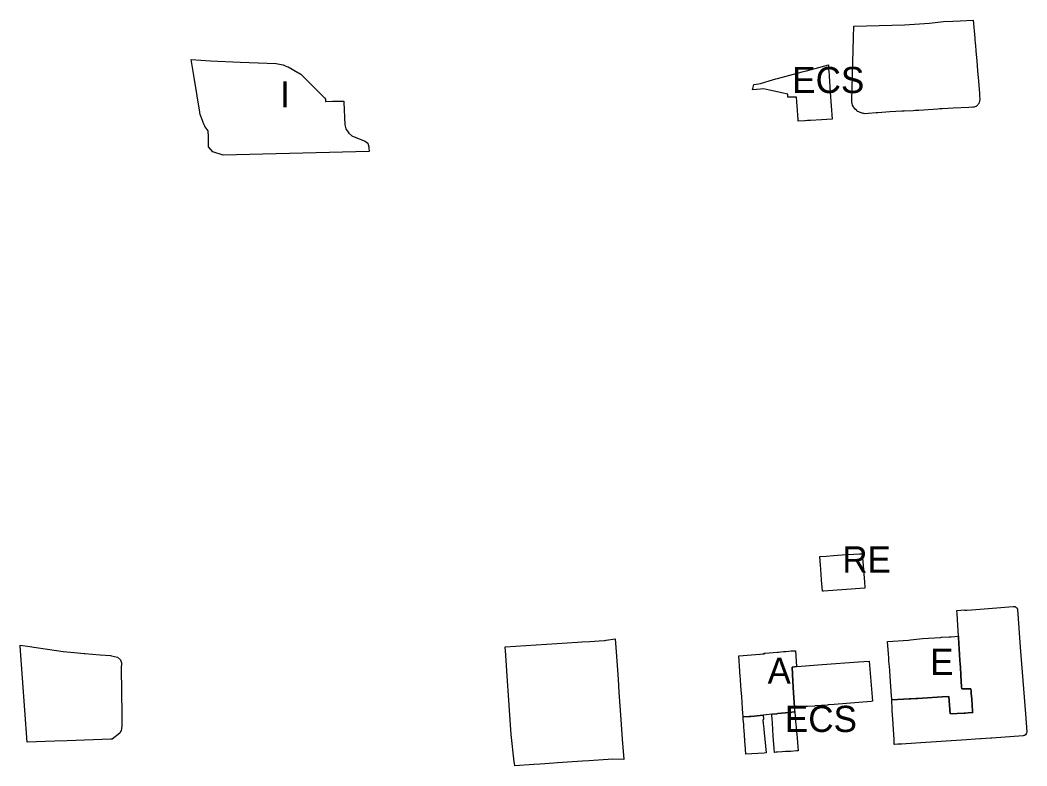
# Model space of a CAD drawing. Extents: x 603332 to 610661, y 4407453 to 4413433.
# Drawn here: x 607234.2 to 607695.4, y 4411729.9 to 4412071.6 of the extents above; entities that cross this region are included whole.
import ezdxf

# ---------------------------------------------------------------- set-up
doc = ezdxf.new("R2010")
doc.units = 0
for name, color, linetype in [('Sistema General-Equipament Privat. Església', 7, 'Continuous'), ('Sistema General-Equipament Públic', 7, 'Continuous'), ('Sistema General-Equipament Públic Socio-cultural', 7, 'Continuous'), ('Sistema General-Equipament Públic-Ajuntament', 7, 'Continuous'), ('Sistema General-Equipament Públic. Sales reunió i espectacles', 7, 'Continuous'), ('Sistema General-Espai Lliure Públic', 7, 'Continuous'), ('Sistema General-Espai Lliure Públic-Sòl Rústic', 7, 'Continuous'), ('Sistema General-Infraestructures', 7, 'Continuous')]:
    doc.layers.add(name, color=color, linetype=linetype)

msp = doc.modelspace()

# ---------------------------------------------------------------- linework, layer by layer
at = {"layer": 'Sistema General-Equipament Privat. Església'}
msp.add_lwpolyline([(607633.47, 4411760.08), (607633.46, 4411760.27), (607633.31, 4411762.33), (607633.21, 4411763.69), (607633.17, 4411764.29), (607632.88, 4411768.41), (607632.52, 4411773.5), (607632.37, 4411775.55), (607632.31, 4411776.45), (607632.2, 4411777.95), (607632.19, 4411778.1), (607632.19, 4411778.13), (607632.18, 4411778.23), (607632.1, 4411779.44), (607631.97, 4411781.23), (607631.57, 4411786.88), (607641.21, 4411787.54), (607642.09, 4411787.6), (607647.54, 4411788.26), (607655.73, 4411788.77), (607656.32, 4411788.81), (607659.75, 4411789.02), (607660.63, 4411789.08), (607664.02, 4411789.33), (607664.04, 4411788.97), (607664.25, 4411785.61), (607664.36, 4411783.76), (607664.55, 4411780.62), (607664.82, 4411776.35), (607664.89, 4411775.23), (607665.13, 4411771.29), (607665.45, 4411766.06), (607665.51, 4411765.15), (607665.63, 4411765.15), (607665.65, 4411765.15), (607665.81, 4411765.15), (607666.48, 4411765.17), (607668.97, 4411765.21), (607669.72, 4411765.22), (607669.76, 4411764.75), (607669.78, 4411764.37), (607669.89, 4411762.99), (607670.08, 4411760.51), (607670.5, 4411754.9), (607670.55, 4411754.26), (607668.44, 4411754.16), (607667.04, 4411754.09), (607666.7, 4411754.08), (607660.18, 4411753.77), (607659.62, 4411761.64), (607656.5, 4411761.45), (607647.48, 4411760.92), (607645.36, 4411760.79), (607644.45, 4411760.73), (607642.21, 4411760.6), (607641.51, 4411760.56)], close=True, dxfattribs=at)
at = {"layer": 'Sistema General-Equipament Públic'}
msp.add_lwpolyline([(607575.9, 4411735.79), (607575.89, 4411735.79), (607575.07, 4411735.74), (607572.06, 4411735.54), (607566.63, 4411735.18), (607566.46, 4411737.59), (607566.18, 4411741.36), (607565.82, 4411746.38), (607565.75, 4411747.28), (607565.63, 4411748.93), (607565.47, 4411751.13), (607565.39, 4411752.34), (607568.14, 4411752.51), (607568.86, 4411752.56), (607570.42, 4411752.73), (607574.53, 4411753.18), (607574.54, 4411753.18), (607574.78, 4411751.06), (607574.42, 4411751.02), (607574.61, 4411749.22), (607574.83, 4411746.86), (607575.03, 4411744.8), (607575.29, 4411742.1), (607575.9, 4411735.8)], close=True, dxfattribs=at)
at = {"layer": 'Sistema General-Equipament Públic Socio-cultural'}
for points in [[(607590.55, 4412025.27), (607590.55, 4412025.51), (607590.56, 4412026.13), (607590.07, 4412032.25), (607589.98, 4412034.11), (607589.86, 4412036.36), (607589.22, 4412036.36), (607587.77, 4412036.37), (607585.78, 4412036.37), (607585.85, 4412037.75), (607582.96, 4412038.3), (607581.74, 4412038.53), (607577.48, 4412039.47), (607574.75, 4412040.05), (607573.36, 4412040), (607569.67, 4412039.72), (607570.22, 4412042.04), (607572.39, 4412042.4), (607573.34, 4412042.56), (607577.23, 4412043.76), (607578.85, 4412044.25), (607580.35, 4412044.71), (607581.06, 4412044.9), (607592.45, 4412047.92), (607593.7, 4412048.25), (607594.35, 4412048.42), (607597.74, 4412049.32), (607598.45, 4412049.51), (607604.41, 4412051.09), (607604.46, 4412050.37), (607604.46, 4412050.29), (607604.56, 4412048.89), (607604.58, 4412048.56), (607604.75, 4412046.1), (607604.76, 4412046.03), (607605.28, 4412038.38), (607606.12, 4412026.25), (607601.26, 4412025.94), (607596.2, 4412025.63), (607594.84, 4412025.54), (607593.83, 4412025.48), (607593.61, 4412025.46)], [(607590.6, 4411736.77), (607589.87, 4411736.72), (607587.25, 4411736.54), (607587.06, 4411736.53), (607586.8, 4411736.52), (607586.38, 4411736.49), (607585.58, 4411736.43), (607584.95, 4411736.39), (607583.31, 4411736.28), (607581.07, 4411736.14), (607580.55, 4411736.1), (607579.84, 4411736.05), (607579.74, 4411736.05), (607579.61, 4411737.78), (607579.17, 4411743.48), (607578.93, 4411746.61), (607578.76, 4411749.54), (607578.66, 4411751.37), (607578.5, 4411753.06), (607578.45, 4411753.57), (607578.46, 4411753.58), (607580.77, 4411753.8), (607581.24, 4411753.84), (607586.45, 4411754.36), (607588.97, 4411754.6), (607588.96, 4411754.75), (607589.06, 4411754.76), (607589.07, 4411754.66), (607589.1, 4411754.17), (607589.21, 4411752.79), (607589.31, 4411751.54), (607589.32, 4411751.37), (607589.32, 4411751.35), (607589.33, 4411751.22), (607589.42, 4411750.2), (607589.53, 4411749.05), (607589.67, 4411747.45), (607589.73, 4411746.75), (607589.74, 4411746.64), (607589.76, 4411746.45), (607589.84, 4411745.58), (607589.88, 4411745.1), (607589.94, 4411744.44)]]:
    msp.add_lwpolyline(points, close=True, dxfattribs=at)
at = {"layer": 'Sistema General-Equipament Públic-Ajuntament'}
msp.add_lwpolyline([(607589.77, 4411775.35), (607587.84, 4411775.14), (607588.19, 4411768.73), (607588.49, 4411763.29), (607588.84, 4411756.76), (607588.95, 4411754.75), (607588.96, 4411754.75), (607588.97, 4411754.6), (607586.45, 4411754.36), (607581.24, 4411753.84), (607580.77, 4411753.8), (607578.46, 4411753.58), (607578.45, 4411753.57), (607575.98, 4411753.32), (607574.54, 4411753.18), (607574.53, 4411753.18), (607570.42, 4411752.73), (607568.86, 4411752.56), (607568.14, 4411752.51), (607565.39, 4411752.34), (607565.37, 4411752.64), (607565.27, 4411753.9), (607565.11, 4411756.18), (607564.71, 4411761.62), (607564.5, 4411764.58), (607564.17, 4411769.19), (607564.12, 4411769.86), (607564.11, 4411769.95), (607564.11, 4411770.03), (607564.06, 4411770.62), (607563.87, 4411773.27), (607563.36, 4411780.33), (607573.01, 4411781.07), (607573.24, 4411781.09), (607574.45, 4411781.17), (607575.1, 4411781.22), (607575.08, 4411781.48), (607575.39, 4411781.51), (607575.4, 4411781.51), (607575.52, 4411781.52), (607581, 4411782), (607581.54, 4411782.05), (607582.7, 4411782.15), (607583.87, 4411782.26), (607584.93, 4411782.35), (607586.26, 4411782.47), (607587.45, 4411782.53), (607589.4, 4411782.63)], close=True, dxfattribs=at)
at = {"layer": 'Sistema General-Equipament Públic. Sales reunió i espectacles'}
msp.add_lwpolyline([(607621.12, 4411811.36), (607602.21, 4411809.9), (607601.73, 4411809.86), (607601.3, 4411814.99), (607601.12, 4411817.68), (607600.98, 4411819.87), (607600.95, 4411820.21), (607600.82, 4411821.71), (607600.51, 4411825.78), (607603.55, 4411826), (607606.77, 4411826.23), (607610.73, 4411826.54), (607618.67, 4411826.99), (607619.98, 4411827.08), (607620.37, 4411821.65), (607620.93, 4411814.01), (607621.09, 4411811.69), (607621.1, 4411811.58), (607621.1, 4411811.52)], close=True, dxfattribs=at)
at = {"layer": 'Sistema General-Espai Lliure Públic'}
for points in [[(607616.07, 4412068.82), (607639.3, 4412069.47), (607650.77, 4412070.28), (607657.19, 4412070.9), (607661.42, 4412071.12), (607664.8, 4412071.29), (607670.8, 4412071.6), (607671.52, 4412063.27), (607671.57, 4412062.71), (607671.57, 4412062.62), (607671.68, 4412061.33), (607671.72, 4412060.93), (607671.73, 4412060.84), (607671.78, 4412060.19), (607672.03, 4412057.33), (607672.41, 4412052.88), (607672.81, 4412048.29), (607673.17, 4412043.63), (607673.61, 4412037.97), (607673.7, 4412036.88), (607673.81, 4412035.39), (607673.72, 4412034.38), (607673.71, 4412034.36), (607673.69, 4412034.29), (607673.55, 4412033.94), (607673.38, 4412033.47), (607673.06, 4412033.02), (607672.87, 4412032.75), (607672.84, 4412032.71), (607672.82, 4412032.68), (607672.07, 4412032.07), (607672.03, 4412032.05), (607672.02, 4412032.04), (607671.25, 4412031.69), (607670.55, 4412031.65), (607668.76, 4412031.57), (607661.58, 4412031.24), (607659.15, 4412031.12), (607656.49, 4412030.95), (607655.42, 4412030.88), (607654.63, 4412030.83), (607645.86, 4412030.25), (607644.37, 4412030.15), (607643.29, 4412030.08), (607639.17, 4412029.96), (607638.15, 4412029.89), (607632.59, 4412029.51), (607627.1, 4412029.14), (607626.33, 4412029.09), (607622.83, 4412028.85), (607620.87, 4412028.72), (607620.64, 4412028.78), (607619.99, 4412028.95), (607619.84, 4412028.99), (607619.81, 4412029), (607618.71, 4412029.41), (607618.62, 4412029.45), (607617.67, 4412029.92), (607617.57, 4412029.99), (607617.56, 4412030), (607617.56, 4412030), (607617.51, 4412030.04), (607617.26, 4412030.27), (607616.71, 4412030.76), (607616.23, 4412031.39), (607616.05, 4412031.61), (607616.03, 4412031.64), (607616.01, 4412031.68), (607615.95, 4412031.81), (607615.54, 4412032.62), (607615.28, 4412033.55), (607615.25, 4412033.69), (607615.23, 4412033.87), (607615.16, 4412034.81), (607615.9, 4412063.58)], [(607633.47, 4411760.08), (607641.51, 4411760.56), (607642.21, 4411760.6), (607644.45, 4411760.73), (607645.36, 4411760.79), (607647.48, 4411760.92), (607656.5, 4411761.45), (607659.62, 4411761.64), (607660.18, 4411753.77), (607666.7, 4411754.08), (607667.04, 4411754.09), (607668.44, 4411754.16), (607670.55, 4411754.26), (607670.5, 4411754.9), (607670.08, 4411760.51), (607669.89, 4411762.99), (607669.78, 4411764.37), (607669.76, 4411764.75), (607669.72, 4411765.22), (607668.97, 4411765.21), (607666.48, 4411765.17), (607665.81, 4411765.15), (607665.65, 4411765.15), (607665.63, 4411765.15), (607665.51, 4411765.15), (607665.45, 4411766.06), (607665.13, 4411771.29), (607664.89, 4411775.23), (607664.82, 4411776.35), (607664.55, 4411780.62), (607664.36, 4411783.76), (607664.25, 4411785.61), (607664.04, 4411788.97), (607664.02, 4411789.33), (607663.38, 4411799.57), (607663.29, 4411801.08), (607666.93, 4411801.31), (607666.94, 4411801.26), (607666.94, 4411801.2), (607667.72, 4411801.26), (607667.81, 4411801.27), (607669.99, 4411801.44), (607681.57, 4411802.34), (607687.15, 4411802.77), (607689.1, 4411802.92), (607689.61, 4411802.92), (607689.78, 4411802.87), (607690.06, 4411802.79), (607690.08, 4411802.78), (607690.09, 4411802.78), (607690.52, 4411802.52), (607690.61, 4411802.43), (607690.67, 4411802.37), (607690.75, 4411802.29), (607690.88, 4411802.16), (607691.12, 4411801.72), (607692.36, 4411784.2), (607694.74, 4411753.8), (607695.36, 4411745.55), (607695.34, 4411745.47), (607695.31, 4411745.28), (607695.26, 4411745.02), (607695.04, 4411744.54), (607694.69, 4411744.13), (607694.25, 4411743.82), (607694.19, 4411743.8), (607694.17, 4411743.79), (607694.03, 4411743.74), (607693.74, 4411743.64), (607679.28, 4411742.64), (607678.78, 4411742.61), (607676.6, 4411742.46), (607674.37, 4411742.32), (607674.05, 4411742.3), (607671.89, 4411742.15), (607667.7, 4411741.88), (607644.49, 4411740.32), (607637.92, 4411739.88), (607637.79, 4411739.87), (607636.21, 4411739.77), (607634.69, 4411739.66), (607634.64, 4411739.66), (607634.53, 4411741.74), (607634.39, 4411744.42), (607634.38, 4411744.51), (607634.37, 4411744.8), (607634.3, 4411745.96), (607634.3, 4411746.02), (607634.29, 4411746.14), (607634.27, 4411746.6), (607633.91, 4411751.31), (607633.65, 4411755.18), (607633.63, 4411755.8)], [(607510.71, 4411732.77), (607505.72, 4411733.01), (607494.76, 4411732.16), (607491.86, 4411732.02), (607480.36, 4411731.27), (607478.61, 4411731.15), (607472.37, 4411730.7), (607469.56, 4411730.5), (607460.76, 4411729.88), (607460.75, 4411729.97), (607460.74, 4411730.05), (607460.61, 4411730.95), (607460.5, 4411731.77), (607459.07, 4411744.24), (607457.86, 4411762.16), (607457.42, 4411768.79), (607456.5, 4411782.82), (607456.41, 4411784.06), (607456.39, 4411784.43), (607489.48, 4411786.5), (607491.45, 4411786.67), (607495.15, 4411786.9), (607499.5, 4411787.18), (607501.82, 4411787.32), (607502.11, 4411787.34), (607502.19, 4411787.35), (607502.61, 4411787.43), (607502.68, 4411787.44), (607506.82, 4411788.15), (607506.97, 4411786.05), (607507.23, 4411782.1), (607507.65, 4411775.87), (607508.07, 4411769.67), (607508.47, 4411763.58), (607508.89, 4411757.39), (607509.35, 4411751.14), (607510.02, 4411742.07)], [(607624.6, 4411759.46), (607624.01, 4411759.41), (607607.04, 4411757.99), (607604.46, 4411757.78), (607603.99, 4411757.73), (607603.99, 4411757.67), (607601.15, 4411757.53), (607598.17, 4411757.37), (607598.17, 4411757.29), (607594.89, 4411757.11), (607593.85, 4411757.05), (607588.84, 4411756.76), (607588.49, 4411763.29), (607588.19, 4411768.73), (607587.84, 4411775.14), (607589.77, 4411775.35), (607591.99, 4411775.54), (607601.6, 4411776.38), (607618.3, 4411777.49), (607623.05, 4411777.8)]]:
    msp.add_lwpolyline(points, close=True, dxfattribs=at)
at = {"layer": 'Sistema General-Espai Lliure Públic-Sòl Rústic'}
msp.add_lwpolyline([(607250.04, 4411741.21), (607237.45, 4411740.74), (607234.16, 4411784.7), (607234.2, 4411785.12), (607238.59, 4411784.55), (607240.48, 4411784.27), (607246.71, 4411783.34), (607253.87, 4411782.28), (607258.86, 4411781.83), (607263.53, 4411781.44), (607263.78, 4411781.41), (607270.8, 4411780.82), (607275.5, 4411780.39), (607275.96, 4411780.35), (607275.97, 4411780.35), (607278.79, 4411779.66), (607280.16, 4411778.51), (607280.18, 4411778.44), (607280.33, 4411777.97), (607280.62, 4411777.06), (607280.48, 4411774.56), (607280.68, 4411753.36), (607280.77, 4411750.79), (607280.7, 4411748.1), (607280.43, 4411745.94), (607280.22, 4411745.6), (607280.2, 4411745.57), (607279.76, 4411744.87), (607276.39, 4411742.19), (607276.06, 4411742.18), (607275.78, 4411742.17), (607275.71, 4411742.16), (607255.71, 4411741.42)], close=True, dxfattribs=at)
at = {"layer": 'Sistema General-Infraestructures'}
msp.add_lwpolyline([(607382.46, 4412034.5), (607382.46, 4412034.3), (607382.47, 4412034.03), (607382.85, 4412023.62), (607383.43, 4412021.75), (607384.72, 4412019.75), (607386.08, 4412018.58), (607387.89, 4412017.87), (607392.28, 4412016.13), (607393.38, 4412015.16), (607393.96, 4412013.48), (607393.98, 4412012.78), (607394.02, 4412011.53), (607394.03, 4412011.43), (607327.17, 4412009.71), (607322.44, 4412011.31), (607320.41, 4412013.57), (607320.42, 4412013.71), (607320.49, 4412014.93), (607320.49, 4412015), (607320.49, 4412018.22), (607320.28, 4412020.92), (607318.94, 4412022.76), (607318.84, 4412022.89), (607318.78, 4412022.97), (607318.39, 4412023.94), (607316.96, 4412027.52), (607316.73, 4412028.1), (607316.71, 4412028.22), (607316.51, 4412029.41), (607314.03, 4412044.44), (607312.54, 4412053.5), (607321.34, 4412052.92), (607334.9, 4412052.39), (607351.43, 4412051.75), (607353.75, 4412051.32), (607354.69, 4412051.15), (607355.34, 4412050.86), (607356.37, 4412050.41), (607356.93, 4412050.16), (607361.33, 4412047.66), (607362.02, 4412047.26), (607362.77, 4412046.84), (607368.2, 4412041.4), (607369.9, 4412039.69), (607370.78, 4412038.81), (607373.5, 4412036.08), (607373.61, 4412035.92), (607374.03, 4412035.33), (607374.11, 4412034.37), (607374.2, 4412034.37), (607377.24, 4412034.48), (607380.93, 4412034.5)], close=True, dxfattribs=at)

# ---------------------------------------------------------------- texts
at = {"layer": 'Sistema General-Equipament Privat. Església'}
msp.add_text('E', height=12, dxfattribs=at).set_placement((607651.06, 4411771.55))
at = {"layer": 'Sistema General-Equipament Públic Socio-cultural'}
for p in [(607587.89, 4412038.18), (607584.52, 4411745.4)]:
    msp.add_text('ECS', height=12, dxfattribs=at).set_placement(p)
at = {"layer": 'Sistema General-Equipament Públic-Ajuntament'}
msp.add_text('A', height=12, dxfattribs=at).set_placement((607576.56, 4411767.48))
at = {"layer": 'Sistema General-Equipament Públic. Sales reunió i espectacles'}
msp.add_text('RE', height=12, dxfattribs=at).set_placement((607610.81, 4411818.47))
at = {"layer": 'Sistema General-Infraestructures'}
msp.add_text('I', height=12, dxfattribs=at).set_placement((607353.28, 4412031.6))

doc.saveas('drawing.dxf')
